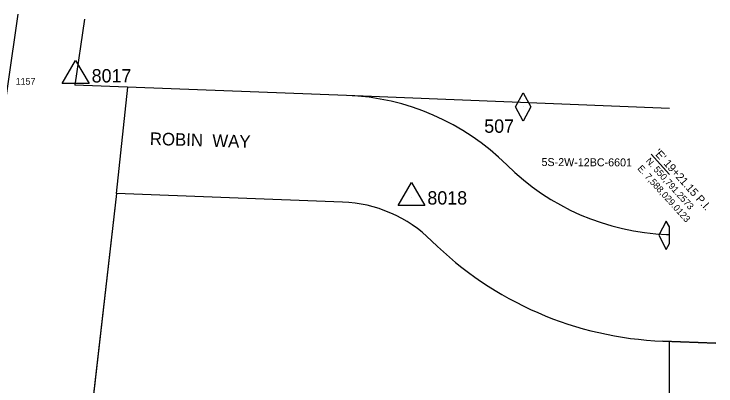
# Model space of a CAD drawing. Extents: x 7586930 to 7587977, y 549274 to 551199.
# Drawn here: x 7587451 to 7587977, y 550729 to 551008 of the extents above; entities that cross this region are included whole.
import ezdxf

# ---------------------------------------------------------------- set-up
doc = ezdxf.new("R2010")
doc.units = 0
for name, color, linetype in [('Default', 7, 'Continuous'), ('E_RDWY_ROAD_NameTx', 7, 'Continuous'), ('E_SURV_ALIGN_MinorTx', 7, 'Continuous'), ('E_SURV_BNDRY_CROW', 7, 'Continuous'), ('E_SURV_BNDRY_OwnerTx', 7, 'Continuous'), ('E_SURV_BNDRY_Property', 7, 'Continuous'), ('E_SURV_MON_FdMonTx', 7, 'Continuous'), ('E_SURV_NTW_SetNtwPt', 7, 'Continuous'), ('E_SURV_NTW_SetNtwPtTx', 7, 'Continuous'), ('E_SURV_NTW_SetStrategicPt', 7, 'Continuous'), ('E_SURV_NTW_SetStrategicPtTx', 7, 'Continuous'), ('P_RW_FILE_AreaShapeRemain', 7, 'Continuous')]:
    doc.layers.add(name, color=color, linetype=linetype)

msp = doc.modelspace()

# ---------------------------------------------------------------- linework, layer by layer
at = {"layer": 'E_SURV_ALIGN_MinorTx'}
msp.add_lwpolyline([(7587942.17, 550887.29), (7587928.4, 550902.51)], dxfattribs=at)
at = {"layer": 'E_SURV_BNDRY_CROW'}
for p, q in [((7587454.09, 551007.61), (7587384.32, 550524.19)), ((7587504.08, 551003.88), (7587496.92, 550954.32)), ((7587700.37, 550946.62), (7587496.92, 550954.32)), ((7587528.03, 550873.08), (7587503.03, 550654.44)), ((7587697.35, 550866.68), (7587528.11, 550873.08))]:
    msp.add_line(p, q, dxfattribs=at)
for points in [[(7587940.33, 550842.42), (7587942.17, 550842.35)], [(7587942.17, 550762.29), (7587937.31, 550762.48)]]:
    msp.add_lwpolyline(points, dxfattribs=at)
for centre, radius, start, end in [((7587693.57, 550766.75), 180, 45.2227, 87.8328), ((7587947.13, 551022.29), 180, 225.2227, 267.8328), ((7587693.57, 550766.75), 100, 45.2227, 87.8328), ((7587947.13, 551022.29), 260, 225.2227, 267.8328)]:
    msp.add_arc(centre, radius, start, end, dxfattribs=at)
at = {"layer": 'E_SURV_BNDRY_OwnerTx'}
for p, q in [((7587937.31, 550762.48), (7587977.06, 550760.97)), ((7587977.06, 550760.97), (7587937.31, 550762.48))]:
    msp.add_line(p, q, dxfattribs=at)
at = {"layer": 'E_SURV_BNDRY_Property'}
for p, q in [((7587528.11, 550873.08), (7587536.53, 550952.81)), ((7587942.17, 550936.76), (7587700.37, 550946.62))]:
    msp.add_line(p, q, dxfattribs=at)
at = {"layer": 'E_SURV_NTW_SetNtwPt'}
for p, q in [((7587487.42, 550955.56), (7587497.42, 550972.88)), ((7587497.42, 550972.88), (7587507.42, 550955.56)), ((7587497.42, 550961.33), (7587497.42, 550961.33)), ((7587507.42, 550955.56), (7587487.42, 550955.56)), ((7587738.89, 550864.02), (7587748.89, 550881.34)), ((7587748.89, 550881.34), (7587758.89, 550864.02)), ((7587748.89, 550869.8), (7587748.89, 550869.8)), ((7587758.89, 550864.02), (7587738.89, 550864.02))]:
    msp.add_line(p, q, dxfattribs=at)
at = {"layer": 'E_SURV_NTW_SetStrategicPt'}
for p, q in [((7587826.96, 550937.97), (7587832.63, 550948.58)), ((7587832.63, 550948.58), (7587838.3, 550937.97)), ((7587832.63, 550948.58), (7587832.63, 550948.58)), ((7587832.63, 550927.37), (7587826.96, 550937.97)), ((7587832.63, 550937.97), (7587832.63, 550937.97)), ((7587838.3, 550937.97), (7587832.63, 550927.37)), ((7587939.83, 550852.4), (7587934.16, 550841.79)), ((7587942.17, 550848.01), (7587939.83, 550852.4)), ((7587939.83, 550852.4), (7587939.83, 550852.4)), ((7587939.83, 550852.4), (7587939.83, 550852.4)), ((7587939.83, 550852.4), (7587939.83, 550852.4)), ((7587942.17, 550835.58), (7587942.17, 550848.01)), ((7587934.16, 550841.79), (7587939.83, 550831.19)), ((7587939.83, 550841.79), (7587939.83, 550841.79)), ((7587939.83, 550831.19), (7587942.17, 550835.58)), ((7587939.83, 550831.19), (7587939.83, 550831.19))]:
    msp.add_line(p, q, dxfattribs=at)
msp.add_lwpolyline([(7587939.83, 550831.19), (7587939.83, 550831.19), (7587939.83, 550831.19)], dxfattribs=at)
at = {"layer": 'P_RW_FILE_AreaShapeRemain'}
for p, q in [((7587937.31, 550762.48), (7587937.3, 550762.48)), ((7587937.31, 550762.48), (7587937.3, 550762.48)), ((7587942.17, 550762.29), (7587937.31, 550762.48)), ((7587942.17, 550762.29), (7587937.31, 550762.48)), ((7587942.17, 550364.37), (7587942.17, 550762.29))]:
    msp.add_line(p, q, dxfattribs=at)
msp.add_lwpolyline([(7587697.35, 550866.68), (7587528.11, 550873.08), (7587503.03, 550654.44), (7587498.41, 550509.6)], dxfattribs=at)
msp.add_lwpolyline([(7587697.35, 550866.68), (7587528.11, 550873.08), (7587503.03, 550654.44), (7587498.41, 550509.6)], dxfattribs=at)
for centre, radius, start, end in [((7587693.57, 550766.75), 100, 45.2227, 87.8328), ((7587693.57, 550766.75), 100, 45.2227, 87.8328), ((7587947.13, 551022.29), 260, 225.2227, 267.8328), ((7587947.13, 551022.29), 260, 225.2227, 267.8328)]:
    msp.add_arc(centre, radius, start, end, dxfattribs=at)

# ---------------------------------------------------------------- texts
at = {"layer": 'Default'}
msp.add_text('5S-2W-12BC-6601', height=6, rotation=359.7425, dxfattribs=at).set_placement((7587846.36, 550893.67))
at = {"layer": 'E_RDWY_ROAD_NameTx'}
msp.add_text('ROBIN  WAY', height=9.4, rotation=358.2706, dxfattribs=at).set_placement((7587552.88, 550909.56))
at = {"layer": 'E_SURV_ALIGN_MinorTx'}
for s, height, p in [("'E' 19+21.15 P.I.", 6, (7587930.29, 550903.23)), ('N. 550,791.2573', 5, (7587924.1, 550897.17)), ('E. 7,588,029.0123', 5, (7587917.92, 550891.58))]:
    msp.add_text(s, height=height, rotation=312.1235, dxfattribs=at).set_placement(p)
at = {"layer": 'E_SURV_MON_FdMonTx'}
msp.add_text('1157', height=5, dxfattribs=at).set_placement((7587452.46, 550954.64))
at = {"layer": 'E_SURV_NTW_SetNtwPtTx'}
for s, p in [('8017', (7587509.42, 550956.33)), ('8018', (7587760.89, 550864.8))]:
    msp.add_text(s, height=10, dxfattribs=at).set_placement(p)
at = {"layer": 'E_SURV_NTW_SetStrategicPtTx'}
msp.add_text('507', height=10, dxfattribs=at).set_placement((7587803.48, 550918.6))

doc.saveas('drawing.dxf')
